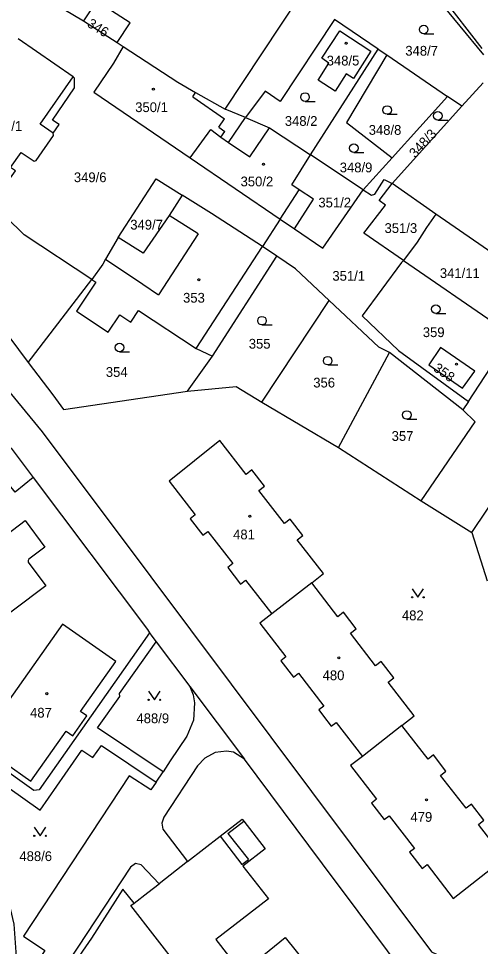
# Model space of a CAD drawing. Extents: x -558358 to -557517, y -1073785 to -1073189.
# Drawn here: x -557990.2 to -557909.7, y -1073433.6 to -1073271.9 of the extents above; entities that cross this region are included whole.
import ezdxf

# ---------------------------------------------------------------- set-up
doc = ezdxf.new("R2010")
doc.units = 0
for name, color, linetype in [('Hranice parcel', 7, 'Continuous'), ('Parcelní čísla', 7, 'Continuous'), ('Vnitřní kresba', 7, 'Continuous'), ('Značky budov', 7, 'Continuous'), ('Značky kultur', 7, 'Continuous')]:
    doc.layers.add(name, color=color, linetype=linetype)

msp = doc.modelspace()

# ---------------------------------------------------------------- linework, layer by layer
at = {"layer": 'Hranice parcel'}
for p, q in [((-557909.08, -1073278.25), (-557930.32, -1073252.64)), ((-557954.2, -1073287.72), (-557935.78, -1073259.94)), ((-557988.45, -1073266.61), (-557978.88, -1073272.32)), ((-557978.88, -1073272.32), (-557973.02, -1073276.12)), ((-557973.02, -1073276.12), (-557971.93, -1073276.83)), ((-557939.28, -1073295.66), (-557927.49, -1073277.3)), ((-557927.49, -1073277.3), (-557926.01, -1073278.28)), ((-557926.01, -1073278.28), (-557915.41, -1073285.51)), ((-557912.91, -1073287.22), (-557909.23, -1073283.14)), ((-557915.41, -1073285.51), (-557925.06, -1073296.21)), ((-557912.91, -1073287.22), (-557915.41, -1073285.51)), ((-557950.63, -1073289.21), (-557954.2, -1073287.72)), ((-557925.08, -1073300.71), (-557912.91, -1073287.22)), ((-557930.1, -1073301.79), (-557939.28, -1073295.66)), ((-557960.27, -1073296.22), (-557944.6, -1073306.89)), ((-557925.06, -1073296.21), (-557930.1, -1073301.79)), ((-557927.31, -1073303.62), (-557925.08, -1073300.71)), ((-557917.44, -1073306), (-557925.08, -1073300.71)), ((-557944.6, -1073306.89), (-557947.68, -1073311.68)), ((-557944.6, -1073306.89), (-557942.12, -1073308.58)), ((-557923.1, -1073314.09), (-557930, -1073309.35)), ((-557945.18, -1073313.34), (-557947.68, -1073311.68)), ((-557956.39, -1073330.78), (-557945.18, -1073313.34)), ((-557923.1, -1073314.09), (-557906.54, -1073325.46)), ((-557988.49, -1073331.84), (-557977.43, -1073317.43)), ((-557947.81, -1073338.78), (-557936.06, -1073321.05)), ((-557911.75, -1073338.65), (-557904.1, -1073326.9)), ((-557960.73, -1073336.87), (-557956.39, -1073330.78)), ((-557934.44, -1073346.66), (-557925.54, -1073330.14)), ((-557912.73, -1073340.1), (-557925.54, -1073330.14)), ((-557911.2, -1073361.51), (-557892.99, -1073334.25)), ((-557947.81, -1073338.78), (-557934.44, -1073346.66)), ((-557911.75, -1073338.65), (-557912.73, -1073340.1)), ((-557934.44, -1073346.66), (-557919.99, -1073355.94)), ((-557919.99, -1073355.94), (-557911.2, -1073361.51)), ((-557911.2, -1073361.51), (-557908.52, -1073369.92)), ((-557939.06, -1073370.25), (-557946.07, -1073375.66)), ((-557967.34, -1073378.97), (-557986.61, -1073406.29)), ((-557972.56, -1073389.56), (-557966.21, -1073380.53)), ((-557966.21, -1073380.53), (-557960.31, -1073388.29)), ((-557960.31, -1073388.29), (-557950.81, -1073400.97)), ((-557960.31, -1073388.29), (-557959.73, -1073389.78)), ((-557923.37, -1073395.09), (-557930.26, -1073400.48)), ((-557950.81, -1073400.97), (-557952.73, -1073399.73)), ((-557966.19, -1073404.96), (-557964.99, -1073403.16)), ((-557965.04, -1073413.14), (-557960.73, -1073418.81)), ((-557965.67, -1073422.67), (-557968.81, -1073419.39)), ((-557960.73, -1073418.81), (-557965.67, -1073422.67)), ((-557970.03, -1073426.04), (-557971.99, -1073423.64))]:
    msp.add_line(p, q, dxfattribs=at)
for points in [[(-557930.24, -1073250.53), (-557916.49, -1073268.06), (-557909.46, -1073277.19)], [(-557973.02, -1073276.12), (-557970.72, -1073272.68), (-557976.62, -1073268.9), (-557978.88, -1073272.32)], [(-557992.18, -1073271.14), (-558017.7, -1073308.66), (-558015.75, -1073309.85), (-558004.08, -1073317.8), (-557996.67, -1073322.48), (-557993.43, -1073325.31), (-557988.49, -1073331.84)], [(-557927.49, -1073277.3), (-557935.12, -1073272.11), (-557944.58, -1073286.41), (-557947.22, -1073284.58), (-557950.63, -1073289.21)], [(-557937.99, -1073282.67), (-557936.08, -1073279.73), (-557937.34, -1073278.85), (-557934.2, -1073274.07), (-557928.77, -1073277.64), (-557931.8, -1073282.4), (-557933.09, -1073281.6), (-557934.98, -1073284.6), (-557937.99, -1073282.67)], [(-557995.47, -1073303.55), (-557992.42, -1073299.14), (-557991.6, -1073299.71), (-557990.74, -1073298.46), (-557991.57, -1073297.9), (-557989.74, -1073295.26), (-557987.45, -1073296.82), (-557987.09, -1073296.7), (-557984.08, -1073292.32), (-557984.13, -1073291.92), (-557983.12, -1073290.42), (-557984.28, -1073289.64), (-557980.42, -1073284.02), (-557980.45, -1073282.32), (-557980.68, -1073282.11), (-557990.25, -1073275.48)], [(-557971.93, -1073276.83), (-557973.65, -1073279.73), (-557977.09, -1073284.77), (-557960.27, -1073296.22)], [(-557971.93, -1073276.83), (-557962.4, -1073283.03), (-557959.33, -1073284.84), (-557954.2, -1073287.72)], [(-557926.01, -1073278.28), (-557933.02, -1073290.08), (-557925.06, -1073296.21)], [(-557960.27, -1073296.22), (-557956.66, -1073291.3), (-557954.92, -1073292.62), (-557953.6, -1073293.52), (-557950.63, -1073289.21)], [(-557950.63, -1073289.21), (-557946.45, -1073290.96), (-557939.28, -1073295.66)], [(-557942.12, -1073308.58), (-557938.8, -1073303.44), (-557941.3, -1073301.76), (-557942.56, -1073300.91), (-557939.28, -1073295.66)], [(-557972.83, -1073310.08), (-557966.21, -1073299.85), (-557961.67, -1073302.72)], [(-557930.1, -1073301.79), (-557928.7, -1073302.72), (-557928.1, -1073302.55), (-557926.47, -1073299.96), (-557925.08, -1073300.71)], [(-557942.12, -1073308.58), (-557937.16, -1073311.96), (-557930.1, -1073301.79)], [(-557977.43, -1073317.43), (-557989.2, -1073309.62), (-557995.47, -1073303.55)], [(-557961.67, -1073302.72), (-557963.96, -1073306.23), (-557968.46, -1073312.83), (-557972.83, -1073310.08)], [(-557947.68, -1073311.68), (-557956.58, -1073305.91), (-557961.67, -1073302.72)], [(-557930, -1073309.35), (-557926.23, -1073304.45), (-557927.31, -1073303.62)], [(-557917.44, -1073306), (-557919.08, -1073308.35), (-557920.7, -1073310.88), (-557923.1, -1073314.09)], [(-557906.54, -1073325.46), (-557900.99, -1073317.38), (-557917.44, -1073306)], [(-557972.83, -1073310.08), (-557975.02, -1073313.87), (-557975.51, -1073314.71), (-557977.43, -1073317.43)], [(-558022.09, -1073311.21), (-558020.08, -1073313.87), (-558000.41, -1073328.2), (-557993.92, -1073334.5), (-557986.04, -1073343.93), (-557967.1, -1073369.2), (-557918.24, -1073434.51), (-557914.64, -1073436.24), (-557909.55, -1073436.22), (-557905.05, -1073434.1), (-557902.57, -1073430.65), (-557891.22, -1073414.37), (-557877.97, -1073395.43)], [(-557936.06, -1073321.05), (-557941.93, -1073315.57), (-557945.18, -1073313.34)], [(-557923.1, -1073314.09), (-557923.42, -1073314.47), (-557930.3, -1073323.72), (-557923.97, -1073329.78), (-557911.75, -1073338.65)], [(-557977.43, -1073317.43), (-557976.74, -1073317.89), (-557980.07, -1073322.91)], [(-557925.54, -1073330.14), (-557927.37, -1073329.18), (-557936.06, -1073321.05)], [(-557980.07, -1073322.91), (-557974.55, -1073326.57), (-557972.53, -1073323.54), (-557970.61, -1073324.82)], [(-557970.61, -1073324.82), (-557969.28, -1073322.81), (-557959.2, -1073329.4), (-557956.39, -1073330.78)], [(-557916.62, -1073329.24), (-557918.71, -1073332.26), (-557912.81, -1073336.33), (-557910.69, -1073333.4), (-557916.62, -1073329.24)], [(-557988.49, -1073331.84), (-557984.2, -1073337.5), (-557982.34, -1073340.07), (-557960.73, -1073336.87)], [(-557960.73, -1073336.87), (-557952.24, -1073336.05), (-557947.81, -1073338.78)], [(-557919.99, -1073355.94), (-557910.58, -1073342.2), (-557912.73, -1073340.1)], [(-557987.64, -1073351.9), (-557990.77, -1073354.47), (-557995.82, -1073348.28), (-557992.92, -1073345.89)], [(-557992.92, -1073345.89), (-557991.47, -1073346.8), (-557987.64, -1073351.9)], [(-557939.06, -1073370.25), (-557937.03, -1073368.65), (-557941.61, -1073362.76), (-557940.64, -1073362.01), (-557942.87, -1073359.14), (-557943.85, -1073359.89), (-557948.29, -1073354.18), (-557947.32, -1073353.42), (-557949.52, -1073350.59), (-557950.49, -1073351.35), (-557955.09, -1073345.44), (-557963.96, -1073352.54), (-557959.4, -1073358.42), (-557960.27, -1073359.1), (-557958.05, -1073361.97), (-557957.18, -1073361.3), (-557952.83, -1073366.91), (-557953.7, -1073367.59), (-557951.48, -1073370.46), (-557950.61, -1073369.79), (-557946.07, -1073375.66)], [(-557987.64, -1073351.9), (-557967.72, -1073378.38), (-557967.34, -1073378.97)], [(-558015.07, -1073378.83), (-558009.7, -1073374.87), (-558009.55, -1073374.62), (-558009.63, -1073374.36), (-558012.72, -1073370.26), (-557996.07, -1073357.8), (-557992.97, -1073361.92), (-557992.74, -1073362.04), (-557992.48, -1073361.98), (-557989.05, -1073359.38), (-557985.61, -1073364.04), (-557988.36, -1073366.15), (-557988.52, -1073366.38), (-557988.48, -1073366.66), (-557985.4, -1073370.76), (-558002.63, -1073383.68), (-558005.71, -1073379.56), (-558005.98, -1073379.48), (-558006.26, -1073379.51), (-558009.96, -1073382.24), (-558012.37, -1073378.99), (-558013.71, -1073380.01)], [(-557923.37, -1073395.09), (-557921.26, -1073393.45), (-557925.78, -1073387.56), (-557924.79, -1073386.8), (-557926.98, -1073383.94), (-557927.98, -1073384.7), (-557932.34, -1073379.01), (-557931.35, -1073378.25), (-557933.54, -1073375.39), (-557934.53, -1073376.15), (-557939.06, -1073370.25)], [(-557946.07, -1073375.66), (-557948.14, -1073377.29), (-557943.62, -1073383.15), (-557944.49, -1073383.82), (-557942.29, -1073386.67), (-557941.42, -1073386), (-557937, -1073391.73), (-557937.87, -1073392.4), (-557937.04, -1073393.49), (-557935.69, -1073395.23), (-557934.82, -1073394.56), (-557930.26, -1073400.48)], [(-557973.25, -1073383.95), (-557982.53, -1073377.43), (-557997.25, -1073398.28), (-557988.03, -1073404.82), (-557981.86, -1073396.11), (-557980.74, -1073396.9), (-557978.29, -1073393.44), (-557979.41, -1073392.65), (-557973.25, -1073383.95)], [(-557967.34, -1073378.97), (-557966.98, -1073379.52), (-557966.21, -1073380.53)], [(-557986.61, -1073406.29), (-557987.5, -1073406.44), (-558001.47, -1073396.48), (-558002.38, -1073393.7), (-558003.7, -1073390.42), (-558005.05, -1073388.34), (-558008.08, -1073385.35), (-558013.71, -1073380.01)], [(-557964.99, -1073403.16), (-557976.4, -1073395.54), (-557972.54, -1073390.07), (-557972.56, -1073389.56)], [(-557959.73, -1073389.78), (-557959.52, -1073391.14), (-557959.72, -1073394.15), (-557960.86, -1073396.95), (-557963.76, -1073401.26), (-557964.99, -1073403.16)], [(-557930.26, -1073400.48), (-557932.35, -1073402.1), (-557927.81, -1073407.96), (-557928.68, -1073408.63), (-557926.46, -1073411.51), (-557925.59, -1073410.83), (-557921.19, -1073416.52), (-557922.06, -1073417.2), (-557919.87, -1073420.02), (-557919, -1073419.35), (-557914.46, -1073425.22), (-557905.47, -1073418.2), (-557910.01, -1073412.34), (-557909.08, -1073411.62), (-557911.27, -1073408.79), (-557912.2, -1073409.51), (-557916.62, -1073403.8), (-557915.7, -1073403.08), (-557917.89, -1073400.24), (-557918.82, -1073400.96), (-557923.37, -1073395.09)], [(-557990.11, -1073441.11), (-557990.95, -1073429.72), (-557991.6, -1073426.99), (-558000.34, -1073399.97), (-557986.42, -1073409.86), (-557979.13, -1073399.38), (-557977.23, -1073400.7), (-557975.75, -1073398.59), (-557966.19, -1073404.96)], [(-557952.73, -1073399.73), (-557953.94, -1073399.59), (-557955.93, -1073399.82), (-557957.72, -1073400.8), (-557958.97, -1073402.15), (-557964.89, -1073411.09), (-557965.23, -1073412.1), (-557965.04, -1073413.14)], [(-557943.74, -1073483.99), (-557922.57, -1073454.37), (-557920.54, -1073448.62), (-557920.67, -1073443.5), (-557923.32, -1073437.76), (-557933.57, -1073424.07), (-557935, -1073422.19), (-557950.81, -1073400.97)], [(-557966.19, -1073404.96), (-557967.15, -1073406.3), (-557970.9, -1073403.86), (-557989.34, -1073431.82), (-557985.62, -1073434.28), (-557990.11, -1073441.11)], [(-557960.73, -1073418.81), (-557955.07, -1073414.41), (-557951.22, -1073411.42), (-557950.93, -1073411.8), (-557947.21, -1073416.59), (-557951.08, -1073419.63), (-557946.63, -1073425.3), (-557955.8, -1073432.39), (-557951.37, -1073438.08), (-557947.44, -1073435.04), (-557943.73, -1073432.04), (-557939.89, -1073436.78), (-557943.7, -1073439.86), (-557943.42, -1073440.21), (-557947.29, -1073443.23), (-557962.81, -1073455.3), (-557971.36, -1073444.52), (-557962.13, -1073437.38), (-557970.6, -1073426.47), (-557970.03, -1073426.04)], [(-557968.81, -1073419.39), (-557969.8, -1073419.14), (-557970.66, -1073419.77), (-557992.19, -1073452.45)], [(-557970.03, -1073426.04), (-557967.63, -1073424.2), (-557965.67, -1073422.67)], [(-557971.99, -1073423.64), (-557977.49, -1073432.15), (-557981.25, -1073437.64), (-557989.89, -1073450.63)]]:
    msp.add_lwpolyline(points, dxfattribs=at)
at = {"layer": 'Vnitřní kresba'}
for p, q in [((-557986.39, -1073290.37), (-557980.68, -1073282.11)), ((-557959.81, -1073285.59), (-557959.33, -1073284.84)), ((-557959.81, -1073285.59), (-557954.3, -1073289.39)), ((-557955.3, -1073290.85), (-557954.3, -1073289.39)), ((-557984.13, -1073291.92), (-557986.39, -1073290.37)), ((-557955.3, -1073290.85), (-557954.25, -1073291.61)), ((-557949.87, -1073296.05), (-557946.45, -1073290.96)), ((-557954.92, -1073292.62), (-557954.25, -1073291.61)), ((-557953.6, -1073293.52), (-557949.87, -1073296.05)), ((-557944.6, -1073306.89), (-557941.3, -1073301.76)), ((-557958.88, -1073309.45), (-557963.96, -1073306.23)), ((-557958.88, -1073309.45), (-557965.78, -1073320.06)), ((-557959.2, -1073329.4), (-557947.68, -1073311.68)), ((-557953.7, -1073413.91), (-557950.93, -1073411.8)), ((-557953.7, -1073413.91), (-557950.12, -1073418.46)), ((-557955.07, -1073414.41), (-557951.25, -1073419.34)), ((-557951.25, -1073419.34), (-557950.12, -1073418.46))]:
    msp.add_line(p, q, dxfattribs=at)
msp.add_lwpolyline([(-557975.02, -1073313.87), (-557968.52, -1073318.2), (-557965.78, -1073320.06)], dxfattribs=at)
at = {"layer": 'Značky budov'}
for centre in [(-557933.08, -1073276.26), (-557966.69, -1073284.23), (-557947.51, -1073297.34), (-557958.76, -1073317.44), (-557913.84, -1073332.14), (-557949.87, -1073358.66), (-557934.36, -1073383.3), (-557985.25, -1073389.56), (-557919.07, -1073408.06)]:
    msp.add_circle(centre, 0.175, dxfattribs=at)
at = {"layer": 'Značky kultur'}
for p, q in [((-557919.58, -1073274.62), (-557917.83, -1073274.62)), ((-557940.26, -1073286.37), (-557938.51, -1073286.37)), ((-557925.93, -1073288.63), (-557924.18, -1073288.63)), ((-557917.1, -1073289.64), (-557915.35, -1073289.64)), ((-557931.76, -1073295.29), (-557930.01, -1073295.29)), ((-557917.45, -1073323.31), (-557915.7, -1073323.31)), ((-557947.76, -1073325.33), (-557946.01, -1073325.33)), ((-557972.6, -1073330.02), (-557970.85, -1073330.02)), ((-557936.31, -1073332.3), (-557934.56, -1073332.3)), ((-557922.53, -1073341.76), (-557920.78, -1073341.76))]:
    msp.add_line(p, q, dxfattribs=at)
for points in [[(-557921.59, -1073371.27), (-557920.59, -1073372.77), (-557919.59, -1073371.27)], [(-557967.51, -1073389.13), (-557966.51, -1073390.63), (-557965.51, -1073389.13)], [(-557987.43, -1073412.84), (-557986.43, -1073414.34), (-557985.43, -1073412.84)]]:
    msp.add_lwpolyline(points, dxfattribs=at)
for centre, radius in [((-557919.58, -1073273.87), 0.75), ((-557940.26, -1073285.62), 0.75), ((-557925.93, -1073287.88), 0.75), ((-557917.1, -1073288.89), 0.75), ((-557931.76, -1073294.54), 0.75), ((-557917.45, -1073322.56), 0.75), ((-557947.76, -1073324.58), 0.75), ((-557972.6, -1073329.27), 0.75), ((-557936.31, -1073331.55), 0.75), ((-557922.53, -1073341.01), 0.75), ((-557921.59, -1073372.77), 0.1), ((-557919.59, -1073372.77), 0.1), ((-557967.51, -1073390.63), 0.1), ((-557965.51, -1073390.63), 0.1), ((-557987.43, -1073414.34), 0.1), ((-557985.43, -1073414.34), 0.1)]:
    msp.add_circle(centre, radius, dxfattribs=at)

# ---------------------------------------------------------------- texts
at = {"layer": 'Parcelní čísla'}
for s, rotation, p in [('346', 328, (-557978.36, -1073273.25)), ('348/3', 47, (-557921.06, -1073296.33)), ('358', 325, (-557918.04, -1073333.2))]:
    msp.add_text(s, height=1.7, rotation=rotation, dxfattribs=at).set_placement(p)
for s, p in [('348/7', (-557922.78, -1073278.41)), ('348/5', (-557936.48, -1073280.12)), ('350/1', (-557969.85, -1073288.24)), ('348/2', (-557943.78, -1073290.64)), ('349/1', (-557995.24, -1073291.52)), ('348/8', (-557929.16, -1073292.2)), ('348/9', (-557934.21, -1073298.74)), ('349/6', (-557980.54, -1073300.45)), ('350/2', (-557951.49, -1073301.18)), ('351/2', (-557937.93, -1073304.85)), ('349/7', (-557970.71, -1073308.71)), ('351/3', (-557926.4, -1073309.3)), ('351/1', (-557935.49, -1073317.62)), ('341/11', (-557916.76, -1073317.15)), ('353', (-557961.51, -1073321.44)), ('359', (-557919.73, -1073327.44)), ('355', (-557950.06, -1073329.45)), ('354', (-557974.97, -1073334.37)), ('356', (-557938.82, -1073336.22)), ('357', (-557925.16, -1073345.52)), ('481', (-557952.79, -1073362.68)), ('482', (-557923.37, -1073376.77)), ('480', (-557937.19, -1073387.21)), ('487', (-557988.17, -1073393.73)), ('488/9', (-557969.63, -1073394.7)), ('479', (-557921.88, -1073411.88)), ('488/6', (-557990.03, -1073418.72))]:
    msp.add_text(s, height=1.7, dxfattribs=at).set_placement(p)

doc.saveas('drawing.dxf')
